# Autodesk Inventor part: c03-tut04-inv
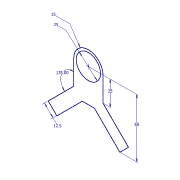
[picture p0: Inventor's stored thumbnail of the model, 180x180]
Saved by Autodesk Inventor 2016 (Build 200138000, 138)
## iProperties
Created: 2010-01
Part Number: c03-tut04-inv
Document SubType Name: Modeling
Designer: CADSoft
Density: 1 g/cm^3
Material: Generic
Appearance: Default
Author: CADSoft
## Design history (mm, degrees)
sketch "Sketch1"
  geometry: L1 (-41.161, -51.161)-(-32.322, -60); L2 (-32.322, -60)-(-6.25, -33.928); L3 (-6.25, -33.928)-(6.25, -33.928); L4 (6.25, -33.928)-(32.322, -60); L5 (32.322, -60)-(41.161, -51.161); L6 (41.161, -51.161)-(15, -25); L7 (15, -25)-(15, 0); L8 (-15, 0)-(-15, -25); L9 (-15, -25)-(-41.161, -51.161); C1 r 12.5 at (0, 0); A1 r 15 centre (0, 0) between (15, 0) and (-15, 0); 2 further points
  constraints: 18 end point, 5 equal length, 3 coincident, 3 parallel, 2 centre point, 2 perpendicular, 2 point on circle, 2 tangent, 1 horizontal, 1 vertical, 1 other
  dimensions: "d0" = 25 distance of L8.start L8.end; "d1" = 60 vertical distance of L1.end A1.centre; "d2" = 12.5 distance of L4.end L5.end; "d3" = 135 deg angle of L6 L7; "d4" = 15 radius of A1; "d5" = 25 diameter of C1
